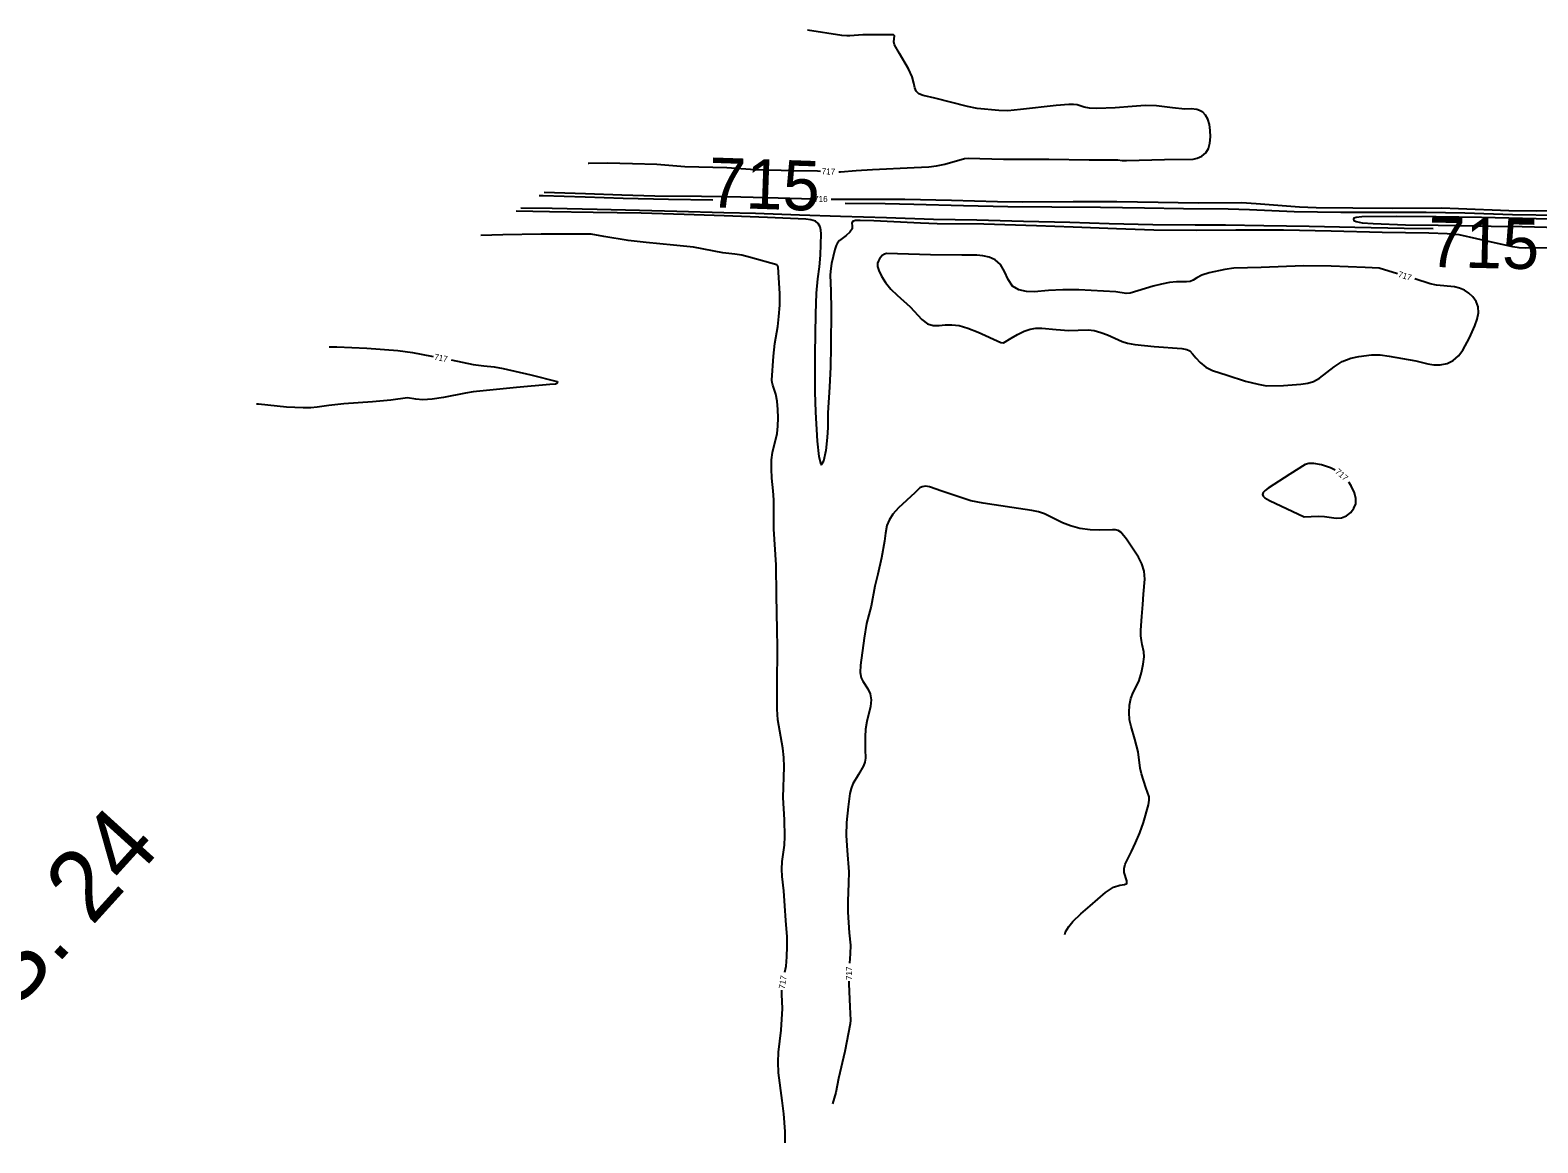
# Model space of a CAD drawing. Extents: x -310467766 to 17062430, y -322263100 to 8322522.
# Drawn here: x 1399656 to 1400655, y 575845 to 576583 of the extents above; entities that cross this region are included whole.
import ezdxf

# ---------------------------------------------------------------- set-up
doc = ezdxf.new("R2010")
doc.units = 0
for name, color, linetype in [('DT_X_Contour_Minor', 7, 'Continuous'), ('Level 19', 7, 'Continuous'), ('Level 40', 7, 'Continuous')]:
    doc.layers.add(name, color=color, linetype=linetype)

msp = doc.modelspace()

# ---------------------------------------------------------------- linework, layer by layer
at = {"layer": 'DT_X_Contour_Minor'}
for points in [[(1400191.41, 576488.87), (1400192.64, 576488.87), (1400203.09, 576489.59), (1400213.82, 576490.44), (1400241.5, 576491.65), (1400251.19, 576492.02), (1400256.27, 576492.71), (1400261.85, 576493.99), (1400274.72, 576497.54), (1400277.26, 576497.77), (1400300.6, 576497.1), (1400330.62, 576497.14), (1400357.37, 576496.74), (1400372.81, 576496.77), (1400376.34, 576496.82), (1400379.24, 576496.37), (1400382.24, 576496.23), (1400407.27, 576496.93), (1400426.37, 576497.22), (1400429.1, 576497.96), (1400432.1, 576499.29), (1400434.73, 576501.37), (1400436.47, 576504.31), (1400437.42, 576507.91), (1400437.77, 576511.95), (1400437.71, 576516.15), (1400437.2, 576520.17), (1400436.16, 576523.68), (1400434.58, 576526.38), (1400432.65, 576528.29), (1400430.61, 576529.53), (1400428.67, 576530.2), (1400425.05, 576530.46), (1400420.88, 576530.42), (1400412.62, 576531.2), (1400402.03, 576532.47), (1400394.43, 576532.75), (1400386.01, 576532.11), (1400374.59, 576531.17), (1400362.55, 576530.73), (1400357.68, 576530.98), (1400354.21, 576531.64), (1400349.46, 576533.18), (1400346.95, 576533.53), (1400343.9, 576533.52), (1400335.56, 576532.7), (1400311.93, 576530), (1400303.53, 576529.29), (1400297.52, 576529.45), (1400283.12, 576530.88), (1400276.83, 576532), (1400255.07, 576537.58), (1400247.37, 576539.47), (1400244.6, 576540.59), (1400242.76, 576542.17), (1400241.88, 576544.45), (1400241.25, 576547.6), (1400240.05, 576551.77), (1400237.7, 576556.95), (1400231.82, 576567.2), (1400228.45, 576573.06), (1400227.96, 576574.88), (1400228.46, 576578.93), (1400227.68, 576579.48), (1400225.76, 576579.68), (1400207.31, 576579.6), (1400201.74, 576579.24), (1400198.83, 576578.84), (1400196.85, 576578.82), (1400193.58, 576579.15), (1400170.71, 576582.68)], [(1400025.28, 576494.45), (1400025.79, 576494.48), (1400038.06, 576494.73), (1400054.69, 576494.38), (1400070.79, 576493.86), (1400089.4, 576492.34), (1400117.22, 576491.6), (1400135.98, 576490.33), (1400161.9, 576489.77), (1400177.48, 576489.38), (1400179.42, 576489.28)], [(1399992.84, 576473.07), (1399995.61, 576473.02), (1400023.29, 576472.22), (1400048.53, 576471.37), (1400078.71, 576470.72), (1400108.08, 576470.33)], [(1399996.12, 576475.31), (1400023.59, 576474.55), (1400047.71, 576473.62), (1400069.48, 576472.98), (1400100.53, 576472.67), (1400126.66, 576472.17), (1400151.3, 576471.5), (1400174.52, 576470.96)], [(1400186.51, 576470.75), (1400202.94, 576470.71), (1400235.21, 576470.63), (1400266.28, 576469.99), (1400296.63, 576469.21), (1400313.45, 576468.99), (1400346.83, 576469.14), (1400375.84, 576469.04), (1400403.07, 576468.74), (1400429.61, 576468.37), (1400458.3, 576468.46), (1400468.21, 576467.9), (1400496.72, 576465.7), (1400507.81, 576465.12), (1400532.18, 576464.87), (1400558.46, 576464.79), (1400590.86, 576464.9), (1400602.3, 576464.6), (1400635.48, 576463.23), (1400653.71, 576462.97), (1400685.68, 576463.1), (1400685.97, 576463.1)], [(1400195.65, 576468), (1400222.28, 576467.8), (1400241.22, 576467.45), (1400274.17, 576466.6), (1400303.45, 576465.9), (1400332.58, 576465.66), (1400364.85, 576465.29), (1400394.04, 576464.96), (1400419.85, 576464.6), (1400449.6, 576464.4), (1400463.75, 576463.89), (1400493.24, 576462.44), (1400524.15, 576462.02), (1400549.3, 576462.01), (1400580.8, 576462.06), (1400606.42, 576461.66), (1400638.09, 576460.64), (1400669.15, 576460.13)], [(1400661.62, 576438.5), (1400646.66, 576438.28), (1400642.47, 576438.51), (1400638.22, 576439.11), (1400626.1, 576441.74), (1400602.69, 576447.14), (1400594.76, 576447.78), (1400582.5, 576448.23), (1400551.68, 576448.72), (1400517.84, 576449.53), (1400486.21, 576450.19), (1400454.62, 576450.25), (1400428.61, 576450.04), (1400400.2, 576450.25), (1400375.59, 576451.13), (1400346.81, 576452.23), (1400322.58, 576453.04), (1400287.64, 576454.05), (1400256.68, 576454.37), (1400245.68, 576454.78), (1400214.72, 576456.34), (1400205.69, 576456.62), (1400202.59, 576456.49), (1400200.52, 576455.93), (1400200.08, 576454.77), (1400200.42, 576453.09), (1400200.28, 576451.05), (1400198.79, 576448.82), (1400196.42, 576446.63), (1400192.06, 576443.21), (1400190.69, 576441.77), (1400189.65, 576439.95), (1400188.78, 576437.44), (1400186.62, 576428.08), (1400186.1, 576424.66), (1400185.85, 576420.58), (1400186.25, 576409.82), (1400186.48, 576397.59), (1400186.13, 576372.83), (1400185.97, 576359.59), (1400185.38, 576346.16), (1400184.26, 576329.07), (1400184.27, 576319.34), (1400183.87, 576312.72), (1400182.81, 576304.26), (1400181.34, 576297), (1400179.78, 576294.77), (1400178.44, 576300.11), (1400177.39, 576310.24), (1400176.17, 576329.54), (1400175.8, 576343.06), (1400175.76, 576367.9), (1400176.36, 576394.82), (1400176.61, 576408.48), (1400177.6, 576417.88), (1400178.72, 576425.76), (1400179.42, 576433.62), (1400179.82, 576447.8), (1400179.64, 576450.1), (1400179.07, 576452.42), (1400177.92, 576454.55), (1400175.95, 576456.18), (1400173.05, 576457.1), (1400169.56, 576457.5), (1400144.24, 576458.53), (1400115.62, 576459.64), (1400089.06, 576460.58), (1400060.43, 576461.43), (1400028.67, 576461.96), (1399999.65, 576462.39), (1399977.58, 576462.67)], [(1400585.51, 576450.94), (1400566.19, 576451.16), (1400533.53, 576451.97), (1400503.29, 576452.67), (1400473.23, 576453.05), (1400447.81, 576453.42), (1400427.73, 576453.52), (1400399.66, 576453.76), (1400370.66, 576454.46), (1400344.67, 576455.19), (1400313.81, 576455.94), (1400282.89, 576456.72), (1400254.2, 576457.24), (1400223.03, 576458.33), (1400192.61, 576459.26), (1400165.36, 576459.99), (1400136.3, 576461.12), (1400115.36, 576461.75), (1400084.24, 576462.52), (1400059.3, 576463.19), (1400031.28, 576463.76), (1400001.51, 576464.49), (1399980.74, 576464.83)], [(1400674.49, 576457.33), (1400653.57, 576457.76), (1400617.34, 576458.61), (1400587.48, 576459.07), (1400560.96, 576459.3), (1400538.21, 576458.98), (1400534.3, 576458.63), (1400532.86, 576458.11), (1400532.64, 576457.44), (1400532.85, 576456.63), (1400534.33, 576455.79), (1400538.37, 576455.04), (1400545.64, 576454.48), (1400567.13, 576453.75), (1400588.77, 576453.42), (1400623.93, 576452.86), (1400644.39, 576452.54), (1400668.7, 576451.84)], [(1400155.67, 575958.53), (1400156.5, 575962.44), (1400157.13, 575968.66), (1400157.37, 575975.43), (1400157.25, 575981.95), (1400156.3, 575992.65), (1400155.62, 576002.46), (1400155.13, 576012.45), (1400153.9, 576021.91), (1400153.66, 576026.72), (1400154.06, 576031.79), (1400155.49, 576042.65), (1400155.8, 576048.34), (1400155.48, 576059.51), (1400154.64, 576074.2), (1400155.36, 576094.54), (1400155.06, 576100.64), (1400154.37, 576106.84), (1400151.17, 576125.8), (1400150.68, 576132.85), (1400150.63, 576148.15), (1400150.96, 576173.95), (1400150.71, 576185.37), (1400150.28, 576208.12), (1400150, 576228.32), (1400148.42, 576252.03), (1400148.54, 576271.49), (1400148.01, 576277.43), (1400147.09, 576285.82), (1400146.78, 576291.95), (1400146.89, 576297.91), (1400147.55, 576302.79), (1400150.55, 576315.41), (1400151.13, 576320.36), (1400151.34, 576325.73), (1400151.13, 576331.36), (1400150.57, 576336.79), (1400149.74, 576341.48), (1400147.86, 576347.53), (1400147.23, 576349.31), (1400147.06, 576350.73), (1400148.29, 576366.62), (1400149.11, 576375.06), (1400151.09, 576386.26), (1400151.84, 576392.96), (1400152.3, 576400.43), (1400152.3, 576407.94), (1400151.36, 576425.85), (1400150.97, 576426.72), (1400150.49, 576427.09), (1400133.05, 576432.07), (1400127.21, 576433.56), (1400122.52, 576434.33), (1400114.65, 576435.12), (1400095.09, 576438.97), (1400081.9, 576440.2), (1400063.73, 576441.93), (1400051.78, 576443.31), (1400035.83, 576446.04), (1400027.46, 576447.4), (1400021.64, 576447.58), (1399994.24, 576447.54), (1399968.9, 576447.07), (1399954.2, 576446.73)], [(1400561.72, 576421.32), (1400549.58, 576424.95), (1400540.24, 576425.49), (1400517.72, 576426.33), (1400499.44, 576426.48), (1400471.31, 576425.38), (1400453.31, 576424.9), (1400447.23, 576424.07), (1400437.03, 576421.81), (1400432.18, 576420.26), (1400428.78, 576418.6), (1400426.42, 576417.11), (1400424.37, 576416.12), (1400422, 576415.82), (1400415.3, 576415.88), (1400410.71, 576415.41), (1400405.45, 576414.44), (1400399.77, 576413.03), (1400384.57, 576408.45), (1400381.89, 576408.16), (1400375.05, 576409.23), (1400350.64, 576410.59), (1400340.05, 576410.72), (1400330.38, 576410.1), (1400320.89, 576409.39), (1400315.78, 576409.52), (1400310.85, 576410.58), (1400306.72, 576413.16), (1400303.73, 576417.54), (1400301.32, 576422.71), (1400298.65, 576427.35), (1400295.14, 576430.45), (1400291.06, 576432.19), (1400286.88, 576433.06), (1400282.9, 576433.49), (1400273.06, 576433.68), (1400252.25, 576433.78), (1400223.15, 576434.68), (1400221.7, 576434.32), (1400220.18, 576433.31), (1400218.44, 576431.18), (1400217.69, 576429.79), (1400217.18, 576428.2), (1400217.18, 576426.18), (1400217.97, 576423.41), (1400219.75, 576419.72), (1400222.47, 576415.47), (1400225.97, 576411.17), (1400230.08, 576407.17), (1400238.8, 576399.26), (1400246.52, 576390.89), (1400250.21, 576388.05), (1400254.01, 576386.95), (1400257.96, 576387.03), (1400262.05, 576387.47), (1400266.36, 576387.54), (1400271.2, 576386.88), (1400276.97, 576385.26), (1400283.75, 576382.6), (1400298.84, 576375.69), (1400300.59, 576375.59), (1400305.83, 576378.68), (1400310.03, 576381.1), (1400314.38, 576383.25), (1400318.31, 576384.59), (1400322.07, 576385.18), (1400326.12, 576385.21), (1400335.6, 576384.39), (1400343.9, 576383.7), (1400350.21, 576383.79), (1400356.82, 576384.05), (1400360.71, 576383.58), (1400365.09, 576382.4), (1400369.5, 576380.77), (1400379.33, 576376.29), (1400382.87, 576375.24), (1400387.74, 576374.36), (1400400.44, 576373.07), (1400418.88, 576371.82), (1400422.14, 576371.19), (1400424.17, 576370.1), (1400425.9, 576368.27), (1400428.09, 576365.56), (1400430.99, 576362.43), (1400434.71, 576359.49), (1400439.25, 576357.2), (1400448.92, 576354.01), (1400460.96, 576350.15), (1400469.36, 576348.15), (1400475, 576347), (1400486.17, 576347.33), (1400497.79, 576348.03), (1400502.31, 576348.68), (1400506.13, 576349.91), (1400510.01, 576352.17), (1400519.69, 576359.59), (1400525.19, 576363.05), (1400530.8, 576365.29), (1400536.12, 576366.51), (1400544.46, 576367.46), (1400550.21, 576367.52)], [(1400550.21, 576367.52), (1400556.28, 576366.68), (1400573.96, 576363.57), (1400581.82, 576361.5), (1400585.77, 576360.9), (1400590.15, 576360.93), (1400594.64, 576361.82), (1400598.77, 576363.76), (1400602.19, 576366.81), (1400604.99, 576370.63), (1400609.51, 576378.78), (1400613.13, 576386.87), (1400614.55, 576391.1), (1400615.4, 576395.32), (1400615.3, 576399.3), (1400614.01, 576402.85), (1400611.8, 576405.9), (1400609.06, 576408.41), (1400606.1, 576410.38), (1400602.94, 576411.78), (1400599.52, 576412.64), (1400587.71, 576413.68), (1400583.44, 576414.6), (1400573.19, 576417.8)], [(1399853.69, 576372.96), (1399858.83, 576372.82), (1399878.67, 576371.86), (1399899.2, 576370.39), (1399908.84, 576369.09), (1399921.58, 576366.73), (1399922.75, 576366.5)], [(1399934.52, 576364.15), (1399949.18, 576361.24), (1399956.25, 576360.28), (1399963.13, 576359.59), (1399969.14, 576358.5), (1399987.42, 576354.28), (1400004.85, 576349.82), (1400005.08, 576349.46), (1400004.62, 576348.66), (1400003.65, 576348.19), (1400000.03, 576347.94), (1399977.92, 576345.81), (1399949.21, 576342.96), (1399944.07, 576342.16), (1399929.48, 576339.2), (1399922.05, 576338.07), (1399915.88, 576337.82), (1399911.21, 576338.16), (1399905.71, 576339.08), (1399894.57, 576337.44), (1399882.37, 576336.32), (1399863.48, 576335.11), (1399853.43, 576334.03), (1399845.68, 576332.84), (1399841.53, 576332.45), (1399836.58, 576332.33), (1399825.51, 576332.86), (1399806.91, 576334.89), (1399805.53, 576334.92)], [(1400520.45, 576291.03), (1400517.28, 576292.69), (1400511.33, 576294.6), (1400506.32, 576295.54), (1400503, 576295.62), (1400500.63, 576294.89), (1400490.36, 576288.47), (1400476.06, 576279.21), (1400474.04, 576277.63), (1400472.78, 576276.29), (1400472.35, 576275.08), (1400472.75, 576273.96), (1400473.8, 576272.9), (1400477, 576271.02), (1400500.01, 576260.29), (1400509.14, 576260.69), (1400513.35, 576260.46), (1400521.15, 576259.32), (1400524.68, 576259.51), (1400527.95, 576260.85), (1400530.77, 576263.11), (1400532.87, 576265.89), (1400534.05, 576268.9), (1400534.19, 576272.27), (1400533.22, 576276.21), (1400531.07, 576280.81), (1400529.44, 576283.08)], [(1400341.31, 575983.39), (1400341.75, 575985.15), (1400343.85, 575988.67), (1400346.54, 575992), (1400351.82, 575997.1), (1400358.04, 576002.4), (1400368.24, 576011.26), (1400373.48, 576014.74), (1400377.8, 576016.24), (1400380.86, 576016.62), (1400382.41, 576017.2), (1400382.39, 576018.95), (1400380.66, 576024.46), (1400380.58, 576027.19), (1400381.39, 576030.09), (1400385.43, 576038.48), (1400388.22, 576044.24), (1400391.01, 576050.76), (1400393.43, 576057.67), (1400396.66, 576069.32), (1400397.28, 576072.56), (1400397.19, 576074.79), (1400395.02, 576080.97), (1400392.07, 576089.83), (1400391.3, 576093.68), (1400389.82, 576104.5), (1400387.7, 576112.8), (1400385.16, 576121.18), (1400384.24, 576125.69), (1400383.84, 576130.55), (1400384.06, 576135.45), (1400384.97, 576139.95), (1400386.57, 576143.82), (1400388.54, 576147.56), (1400390.5, 576151.84), (1400392.13, 576157.07), (1400393.26, 576162.57), (1400393.81, 576167.39), (1400393.74, 576170.86), (1400392.61, 576175.64), (1400392.04, 576178.23), (1400391.68, 576181.37), (1400391.61, 576185.16), (1400392.35, 576194.28), (1400392.94, 576202.04), (1400393.34, 576208.98), (1400394.21, 576218.89), (1400393.84, 576224.17), (1400392.35, 576229), (1400390.03, 576233.45), (1400382.09, 576245.39), (1400378.49, 576249.95), (1400376.66, 576251.22), (1400374.97, 576251.5), (1400372.83, 576251.55), (1400364.54, 576251.46), (1400358.02, 576251.66), (1400351.25, 576252.47), (1400345.13, 576254.14), (1400339.82, 576256.32), (1400327.75, 576262.14), (1400323.85, 576263.44), (1400319.34, 576264.47), (1400306.23, 576266.46), (1400287.27, 576269.18), (1400278.97, 576270.88), (1400259.77, 576277.24), (1400251.67, 576280.02), (1400248.86, 576280.44), (1400246.84, 576280.16), (1400245.26, 576279.33), (1400241.91, 576276.21), (1400231, 576266.25), (1400227.26, 576262.07), (1400224.79, 576258.03), (1400223.43, 576254.42), (1400222.47, 576249.48), (1400221.75, 576244.12), (1400219.77, 576232.97), (1400217.35, 576222.28), (1400215.35, 576214.23), (1400212.96, 576200.95), (1400209.79, 576189.58), (1400208.28, 576179.92), (1400205.86, 576161.97), (1400205.64, 576157.02), (1400206.23, 576153.63), (1400207.47, 576151.24), (1400210.84, 576146.27), (1400212.25, 576142.92), (1400212.87, 576139.01), (1400212.4, 576134.61), (1400210.04, 576124.7), (1400209.24, 576119.45), (1400208.87, 576114.35), (1400209.07, 576106.04), (1400209.25, 576100.26), (1400208.75, 576097.75), (1400207.75, 576095.24), (1400204.46, 576089.56), (1400200.87, 576083.25)], [(1400200.87, 576083.25), (1400199.68, 576080.19), (1400198.86, 576076.89), (1400197.6, 576068.05), (1400196.62, 576057.63), (1400196.43, 576049), (1400197.09, 576039.09), (1400198.13, 576024.88), (1400197.92, 576017.53), (1400197.41, 576005.57), (1400197.44, 575998.37), (1400198.41, 575984.56), (1400199.24, 575976.35), (1400199.06, 575970.73), (1400198.66, 575964.55)], [(1400156, 575845.42), (1400155.9, 575853.02), (1400155.03, 575864.55), (1400153.97, 575873.46), (1400151.59, 575891.81), (1400151.25, 575898.94), (1400151.58, 575905.51), (1400153.35, 575920.12), (1400154.09, 575934.46), (1400153.64, 575943.68), (1400153.72, 575946.69)], [(1400198.17, 575952.56), (1400198.13, 575950.87), (1400198.77, 575935.54), (1400199.28, 575926.6), (1400199.1, 575924.35), (1400195.56, 575906.02), (1400191.39, 575888.05), (1400189.51, 575878.86), (1400187.28, 575871.34)]]:
    msp.add_lwpolyline(points, dxfattribs=at)

# ---------------------------------------------------------------- texts
at = {"layer": 'Level 19'}
for s, height, rotation, p in [('715', 33, 358.0356, (1400104.83, 576465.41)), ('717', 4, 357.24491, (1400180.06, 576487.25)), ('716', 4, 358.64866, (1400175.12, 576468.94)), ('715', 33, 358.70023, (1400581.76, 576425.86)), ('717', 4, 342.64595, (1400561.85, 576419.25)), ('717', 4, 348.74222, (1399923.09, 576364.39)), ('717', 4, 318.27806, (1400520.15, 576289.58)), ('717', 4, 80.86153, (1400155.57, 575947.15)), ('717', 4, 88.88294, (1400200.18, 575953.26))]:
    msp.add_text(s, height=height, rotation=rotation, dxfattribs=at).set_placement(p)
at = {"layer": 'Level 40'}
msp.add_text('U.S. 24', height=46.8, rotation=47.81131, dxfattribs=at).set_placement((1399602.99, 575885.5))

doc.saveas('drawing.dxf')
